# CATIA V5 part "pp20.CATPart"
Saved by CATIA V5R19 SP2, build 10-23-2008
Part number: pp20
Publications: "Line.1", "Point.2", "Plane.1", "Line.2", "Point.4", "Sketch.3"
Bounding box of the stored display mesh (mm): x 0 to 20, y -422 to 0, z -52 to 50
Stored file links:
  C:\Users\Welcome\Documents\thinkm2\pp20.CATPart
  C:\Users\Welcome\Documents\thinkm2\Brasmeca.CATProduct
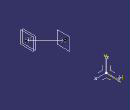
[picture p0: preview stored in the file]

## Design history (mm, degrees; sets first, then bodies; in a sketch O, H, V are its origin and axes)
AxisSystem1: origin (0, 0, 0), X (1, 0, 0), Y (0, 1, 0), Z (0, 0, 1)
Set1
  Point1: linked copy from another document
  Point2: linked copy from another document
  Plane1: linked copy from another document
  Line1: linked copy from another document
  Plane2: linked copy from another document
Body1 (main body)
  Line2: type PtDir, RefPoint Point1, Direction edge [XY plane of AxisSystem1 | ZX plane of AxisSystem1], Start 0, End 20
  Point3: type OnCurve, Support Line2, Length 15
  Plane3: type Normal, Curve Line2, RefPoint Point3
  Line3: type PtPt, FirstPoint Point3, SecondPoint Point2
  Sketch1 on Plane2, origin (5, 0, 0), H (0, 1, 0), V (0, 0, 1)
    circle A1 centre (-420, -50) radius 2
    reference projected point E1 (-420, -50) from Line2
    radius A1 = 2
    distance A1 E1 = 2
